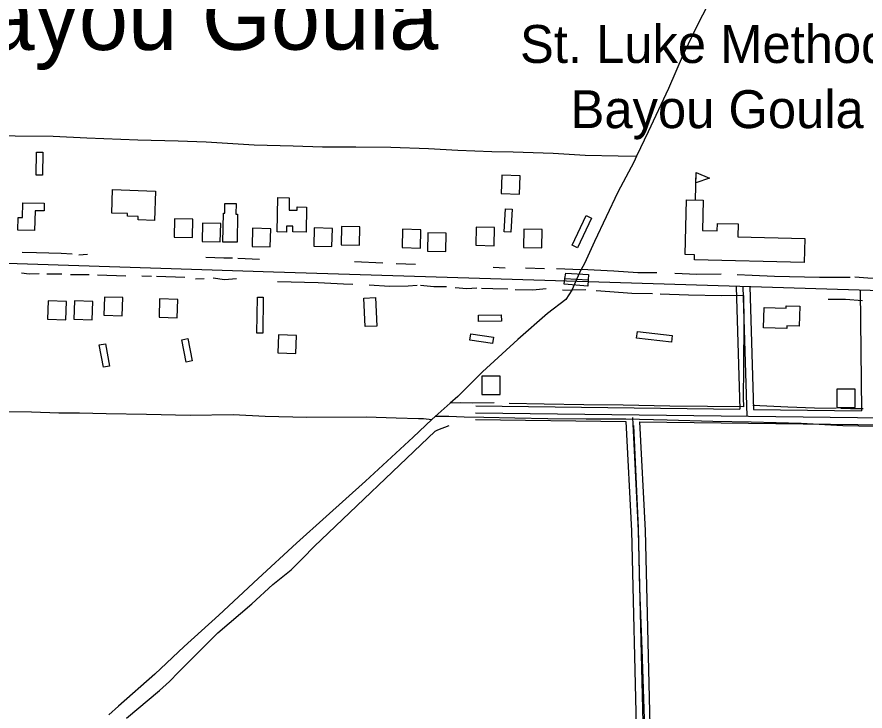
# Model space of a CAD drawing. Extents: x 3324104 to 3361979, y 612876 to 638273.
# Drawn here: x 3329433 to 3331289, y 620956 to 622475 of the extents above; entities that cross this region are included whole.
import ezdxf

# ---------------------------------------------------------------- set-up
doc = ezdxf.new("R2010")
doc.units = 0
for name, color, linetype in [('V-BLDG-IDEN', 7, 'Continuous'), ('V-BLDG-OTLN', 7, 'Continuous'), ('V-BRDG-OTLN', 7, 'Continuous'), ('V-DTCH-CNTR', 7, 'Continuous'), ('V-ROAD-CNTR', 7, 'Continuous'), ('V-SITE-OTLN-IDEN', 7, 'Continuous'), ('V-TOPO-GNAM-IDEN', 7, 'Continuous'), ('V-TOPO-SHOR', 7, 'Continuous')]:
    doc.layers.add(name, color=color, linetype=linetype)

msp = doc.modelspace()

# ---------------------------------------------------------------- linework, layer by layer
at = {"layer": 'V-BLDG-OTLN'}
msp.add_line((3330917.3, 622074.8), (3330918.8, 622134.8), dxfattribs=at)
for points in [[(3329489.4, 622178.9), (3329488.7, 622128.9), (3329474.7, 622129.1), (3329475.4, 622179.1)], [(3330492.6, 622088.5), (3330532.6, 622087.5), (3330533.6, 622127.5), (3330493.6, 622128.5)], [(3330918.8, 622134.8), (3330948.5, 622122.4), (3330918.2, 622111.7)], [(3329641.6, 622097.1), (3329736, 622094.1), (3329733.9, 622029.6), (3329697.8, 622030.7), (3329698.1, 622038.4), (3329674.3, 622039.2), (3329674.5, 622044.8), (3329640, 622045.9)], [(3329472.5, 622050.9), (3329471.3, 622007.4), (3329434.3, 622008.4), (3329435, 622036.2), (3329444.5, 622035.9), (3329445.4, 622068.6), (3329492.4, 622067.3), (3329491.9, 622050.4)], [(3329883.4, 621982.4), (3329884.4, 622045.8), (3329887.4, 622045.7), (3329887.7, 622066.9), (3329912.3, 622066.6), (3329911.9, 622043.8), (3329915.4, 622043.7), (3329914.4, 621981.9)], [(3330002, 622004.6), (3330003.6, 622079.8), (3330028.5, 622079.3), (3330028, 622052.4), (3330045.9, 622052.1), (3330046, 622059.5), (3330066.6, 622059.1), (3330065.5, 622004.1), (3330036.4, 622004.7), (3330036.6, 622017.2), (3330022.6, 622017.5), (3330022.3, 622004.2)], [(3331155.6, 621937.7), (3330915.1, 621943.5), (3330915.4, 621954.8), (3330894.8, 621955.3), (3330897.7, 622075.2), (3330934.6, 622074.4), (3330933, 622007.6), (3330965.2, 622006.9), (3330965.6, 622023.4), (3331011.1, 622022.3), (3331010.5, 621993.7), (3331156.9, 621990.2)], [(3330516, 622054.2), (3330513.1, 622004.3), (3330499.1, 622005.1), (3330502.1, 622055)], [(3329776.6, 621993.4), (3329816.6, 621992.5), (3329817.6, 622032.5), (3329777.6, 622033.4)], [(3330647.6, 621975.3), (3330678.1, 622040.4), (3330690, 622034.8), (3330659.5, 621969.8)], [(3329837.6, 621983.9), (3329877.6, 621983), (3329878.6, 622023), (3329838.6, 622023.9)], [(3329947.1, 621972.6), (3329987.1, 621971.7), (3329988.1, 622011.7), (3329948.1, 622012.6)], [(3330082, 621973.3), (3330122, 621972.4), (3330123, 622012.4), (3330083, 622013.3)], [(3330141.9, 621976.4), (3330181.9, 621975.4), (3330182.9, 622015.4), (3330142.9, 622016.4)], [(3330275.7, 621970.4), (3330315.7, 621969.4), (3330316.6, 622009.4), (3330276.6, 622010.4)], [(3330436.8, 621975.3), (3330476.8, 621974.4), (3330477.8, 622014.4), (3330437.8, 622015.3)], [(3330541.2, 621970.7), (3330581.1, 621969.8), (3330582.1, 622009.8), (3330542.1, 622010.7)], [(3330331.1, 621962.5), (3330371.1, 621961.6), (3330372.1, 622001.6), (3330332.1, 622002.5)], [(3329664.1, 621860.7), (3329624.1, 621862.1), (3329622.6, 621822.2), (3329662.6, 621820.7)], [(3329957.8, 621783.2), (3329958.7, 621862.1), (3329971.3, 621861.9), (3329970.4, 621783.1)], [(3330217.3, 621861), (3330220, 621798.3), (3330194.3, 621797.3), (3330191.7, 621859.9)], [(3329541.2, 621852.1), (3329501.2, 621853.5), (3329499.8, 621813.5), (3329539.8, 621812.1)], [(3329598.4, 621852), (3329558.5, 621853.5), (3329557, 621813.5), (3329597, 621812)], [(3329784.9, 621856.8), (3329744.9, 621858.3), (3329743.5, 621818.3), (3329783.4, 621816.9)], [(3331067.9, 621839.4), (3331115.8, 621837.9), (3331115.9, 621842.8), (3331145.8, 621841.9), (3331144.4, 621798.4), (3331117.5, 621799.3), (3331117.3, 621792.9), (3331066.5, 621794.5)], [(3330442.5, 621822.5), (3330492.5, 621823.2), (3330492.7, 621809.2), (3330442.7, 621808.5)], [(3330790.4, 621786.9), (3330866.4, 621777.9), (3330864.7, 621763.1), (3330788.7, 621772.1)], [(3329806.9, 621771.3), (3329816.4, 621722.2), (3329802.7, 621719.6), (3329793.2, 621768.7)], [(3330044.7, 621778.2), (3330004.7, 621779.7), (3330003.3, 621739.7), (3330043.2, 621738.2)], [(3330426, 621781.6), (3330475.5, 621774.3), (3330473.4, 621760.4), (3330424, 621767.7)], [(3329626.7, 621759.8), (3329635.5, 621710.6), (3329621.7, 621708.2), (3329612.9, 621757.4)], [(3330450, 621648.9), (3330490, 621648.8), (3330490.1, 621688.8), (3330450.1, 621688.9)], [(3331226.7, 621620.2), (3331266.7, 621620.1), (3331266.8, 621660.1), (3331226.8, 621660.2)]]:
    msp.add_lwpolyline(points, close=True, dxfattribs=at)
at = {"layer": 'V-BRDG-OTLN'}
msp.add_line((3330631.7, 621902.6), (3330682.8, 621899.5), dxfattribs=at)
msp.add_lwpolyline([(3330682.2, 621886.2), (3330629.9, 621890.4), (3330631.7, 621902.6), (3330633.5, 621914.5), (3330683.2, 621911.1), (3330682.8, 621899.5)], close=True, dxfattribs=at)
at = {"layer": 'V-DTCH-CNTR'}
for points in [[(3330083, 621316.1), (3330348.1, 621568.2), (3330353.7, 621571.1), (3330378.6, 621581)], [(3330792.6, 621357.2), (3330784.3, 621549), (3330782.7, 621581)], [(3330828.8, 620423.5), (3330824, 620535.8), (3330816.7, 620642.6), (3330812, 620771.7), (3330805.9, 620939), (3330800.5, 621091.1), (3330795.8, 621223.4), (3330792.6, 621357.2)], [(3329672, 620940), (3329744.4, 621000.8), (3329751.8, 621007.2), (3329759, 621013.8), (3329766.1, 621020.5), (3329773, 621027.4), (3329779.7, 621034.5), (3329872.3, 621126.7), (3329946.8, 621190.3), (3329992.5, 621232.6), (3330032.5, 621265), (3330058.1, 621290.4), (3330083, 621316.1)]]:
    msp.add_lwpolyline(points, dxfattribs=at)
at = {"layer": 'V-ROAD-CNTR'}
for points in [[(3332722.7, 621829.2), (3331917.1, 621857.3), (3329994.2, 621916.4), (3328221.8, 621973.8)], [(3331006.2, 621884.4), (3331014.4, 621616.5)], [(3331021.2, 621884.8), (3331029.9, 621601.3)], [(3331036.2, 621885.3), (3331044.4, 621616.1)], [(3331277.9, 621876.3), (3331281.1, 621613.1)], [(3330436.6, 621623.8), (3331014.4, 621616.5)], [(3330436.4, 621608.8), (3331451.3, 621596), (3332550.8, 621581.8)], [(3330779.6, 621598.6), (3330792.2, 621350.6), (3330814.4, 620421.5)], [(3331044.4, 621616.1), (3331281.1, 621613.1)], [(3330436.2, 621593.8), (3330765, 621589.6)], [(3330765, 621589.6), (3330777.2, 621350), (3330799.1, 620434.2)], [(3330795.1, 621589.2), (3331451.2, 621581), (3332550.6, 621566.8)], [(3330795.1, 621589.2), (3330807.2, 621351.1), (3330829, 620436.4)]]:
    msp.add_lwpolyline(points, dxfattribs=at)
at = {"layer": 'V-TOPO-SHOR'}
for p, q in [((3329568, 621954.5), (3329587.1, 621955.8)), ((3329916.1, 621947.4), (3329963.4, 621944.9)), ((3330171.4, 621939.7), (3330233.6, 621937.3)), ((3330262.6, 621935.4), (3330304.9, 621934)), ((3330474.4, 621927.4), (3330501, 621926.3)), ((3330545.3, 621925.8), (3330586.8, 621924.9)), ((3330613.3, 621924.2), (3330667.5, 621922.7)), ((3329498.3, 621913), (3329530.6, 621913.2)), ((3329550.1, 621911.7), (3329590.7, 621911.5)), ((3329608.9, 621910.4), (3329671.1, 621908.8)), ((3329705.9, 621908.6), (3329727.1, 621908)), ((3329737.8, 621907.6), (3329800, 621905.6)), ((3329823.6, 621902), (3329842.3, 621902.6)), ((3330626.4, 621878.1), (3330646.6, 621876.9)), ((3330677.8, 621878.1), (3330646.6, 621876.9)), ((3330730, 621873.1), (3330700.2, 621875.5))]:
    msp.add_line(p, q, dxfattribs=at)
for points in [[(3330959.5, 622531.3), (3330923.9, 622462.6), (3330890.5, 622392.8), (3330858.2, 622318.4), (3330814.2, 622223.6), (3330788.5, 622170.3), (3330782.3, 622157.5), (3330747.6, 622091.8), (3330696.6, 621983.7), (3330674.5, 621935.4), (3330667.5, 621922.7), (3330666.7, 621921.3), (3330646.6, 621876.9), (3330633.6, 621856.4), (3330593.7, 621826.3), (3330529, 621769.1), (3330451.2, 621698.1), (3330397.7, 621644.7), (3330380.6, 621629.6), (3330347.5, 621600.6), (3330340.2, 621593.9), (3330299.7, 621555.7), (3330195.6, 621458.8), (3330109.1, 621381.5), (3330044.5, 621323.5), (3329960.5, 621245.8), (3329874.1, 621166), (3329798.7, 621097.1), (3329734.1, 621036.6), (3329654.6, 620966.4), (3329634, 620947.2)], [(3329246, 622230.2), (3329285.4, 622223.6), (3329318.9, 622219), (3329371, 622217.3), (3329428.9, 622215), (3329511.8, 622214), (3329585.7, 622210.8), (3329697.3, 622206.3), (3329785.5, 622204.3), (3329846.7, 622201.5), (3329951.9, 622195.4), (3330036.9, 622192.8), (3330101.3, 622190.6), (3330174.1, 622191.1), (3330251.1, 622190.1), (3330333, 622186.9), (3330397.8, 622183.7), (3330472.2, 622180.5), (3330518.5, 622179.8), (3330606.2, 622176.7), (3330675.8, 622172.9), (3330748.6, 622170.8), (3330788.5, 622170.3)], [(3329444.1, 621960.2), (3329475.7, 621959.2), (3329529.6, 621957.9), (3329553.1, 621956.4)], [(3329845.7, 621949), (3329885.6, 621947.6), (3329904.1, 621947.8)], [(3329442.8, 621915), (3329459.3, 621912.5), (3329480.9, 621913.7)], [(3330833, 621915.4), (3330791.7, 621915.2), (3330739, 621918.9), (3330667.5, 621922.7)], [(3329862.2, 621903.9), (3329886.6, 621900.2), (3329913.1, 621902.7)], [(3330002.7, 621896.3), (3330091.8, 621893.8), (3330146.9, 621890.9), (3330167.7, 621890.4)], [(3330973.4, 621912.3), (3330920.2, 621911.1), (3330872.3, 621913.7)], [(3331255.7, 621905.2), (3331189.1, 621905.1), (3331090.5, 621907.3), (3331041.2, 621909.1), (3331008.7, 621910.9)], [(3331661, 621892.4), (3331598.6, 621892.3), (3331524, 621894.3), (3331440.7, 621897.4), (3331352, 621900.5), (3331294.4, 621903.4), (3331266.5, 621905.3)], [(3330203.3, 621889), (3330247.6, 621886.2), (3330289, 621886.5), (3330308.6, 621888.1)], [(3330316, 621888.1), (3330345, 621885.3), (3330372.4, 621885.2)], [(3330391.5, 621883.3), (3330417.5, 621880.8), (3330438.7, 621882)], [(3330449.5, 621881.6), (3330473.9, 621880.4), (3330506.7, 621880)], [(3330522.9, 621878.8), (3330561.8, 621878.1), (3330590.8, 621881)], [(3331022.6, 621865.7), (3331023.4, 621808.6), (3331022.3, 621706.8), (3331021.9, 621641.3), (3331022.5, 621622), (3330943.8, 621622.8), (3330861.4, 621622.9), (3330758.9, 621625.2), (3330673.1, 621626), (3330586.2, 621627.7), (3330509.6, 621628.7)], [(3330823.3, 621869.4), (3330778.5, 621870.1), (3330730, 621873.1)], [(3331022.6, 621865.7), (3330974.2, 621864.9), (3330902.5, 621866.5), (3330839.9, 621868.5)], [(3331283.1, 621854), (3331246, 621856.5), (3331208.1, 621856.4)], [(3330476.8, 621630.3), (3330428.9, 621629.9), (3330402.4, 621630.4), (3330380.6, 621629.6)], [(3331225.7, 621618), (3331177.6, 621619.1), (3331119.4, 621620.9), (3331043.2, 621624.3)], [(3331284.3, 621617.3), (3331256.7, 621617.1), (3331235.4, 621618)], [(3329383, 621611.8), (3329464.3, 621610.6), (3329524.3, 621608.7), (3329569.4, 621608.3), (3329627.6, 621606.9), (3329716, 621606), (3329811.9, 621603.7), (3329905.9, 621604.8), (3329976, 621601.5), (3330066.3, 621598.8), (3330197.2, 621599.8), (3330262.8, 621597.6), (3330311.3, 621596.5), (3330322.1, 621596.2), (3330340.2, 621593.9)], [(3331700.1, 621577.9), (3331646, 621576.5), (3331581, 621576.1), (3331486.5, 621577.5), (3331401.1, 621580.2), (3331309.9, 621578.7), (3331239.9, 621580.3), (3331149.1, 621585), (3331039.7, 621587.9), (3330955.2, 621589.4), (3330855.7, 621592.4), (3330765.3, 621594.7), (3330678.3, 621594.9), (3330594.6, 621595.5), (3330522.1, 621597.1), (3330454.1, 621598.3), (3330411.4, 621599.2), (3330377.9, 621600.6), (3330347.5, 621600.6)]]:
    msp.add_lwpolyline(points, dxfattribs=at)

# ---------------------------------------------------------------- texts
at = {"layer": 'V-BLDG-IDEN'}
msp.add_text('Bayou Goula Sch.', height=83, dxfattribs=at).set_placement((3330644.1, 622231.8))
at = {"layer": 'V-SITE-OTLN-IDEN'}
msp.add_text('St. Luke Methodist Ch.', height=83, rotation=359.9873, dxfattribs=at).set_placement((3330533.5, 622374.5))
at = {"layer": 'V-TOPO-GNAM-IDEN'}
msp.add_text('Bayou Goula', height=145, rotation=0.0909, dxfattribs=at).set_placement((3329233.9, 622402.3))

doc.saveas('drawing.dxf')
